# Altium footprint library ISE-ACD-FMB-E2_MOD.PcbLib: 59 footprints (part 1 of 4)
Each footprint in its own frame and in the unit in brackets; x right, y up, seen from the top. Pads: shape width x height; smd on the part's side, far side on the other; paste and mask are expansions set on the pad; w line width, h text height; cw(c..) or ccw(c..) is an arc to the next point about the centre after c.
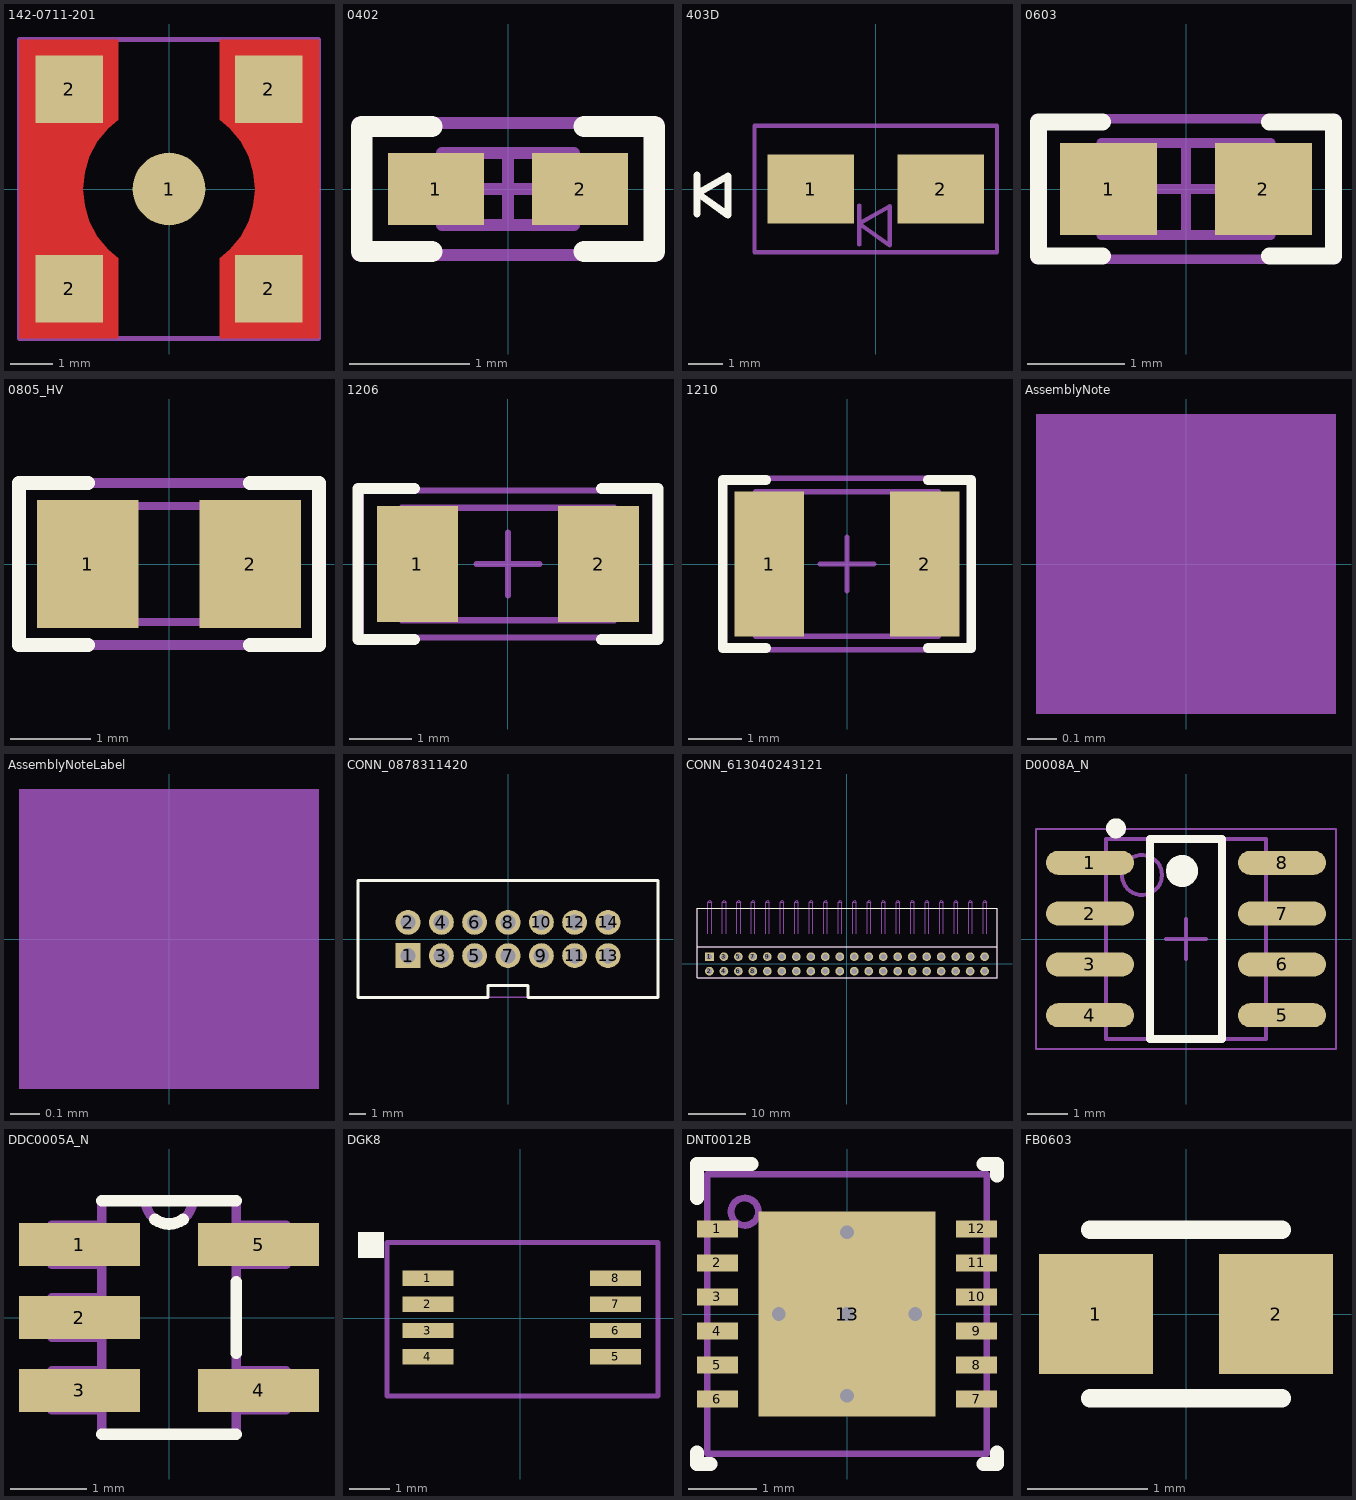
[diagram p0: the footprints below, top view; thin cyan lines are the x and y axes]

## 142-0711-201 [mil] "Emerson Connectivity recommended land pattern"
height 353
pads (5):
  round 68 smd: 1(0,0)
  rect 63x63 smd: 2(-93.5,-93.5) 2(-93.5,93.5) 2(93.5,-93.5) 2(93.5,93.5)
Top Layer:
  region: 140.5,-140 47.5,-140 47.5,-64.83 57.02,-57.02 67.05,-44.8 74.5,-30.86 79.09,-15.73 80.64,0 79.09,15.73 74.5,30.86 67.05,44.8 57.02,57.02 47.5,64.83 47.5,140 140.5,140
  region: -47.5,64.83 -57.02,57.02 -67.05,44.8 -74.5,30.86 -79.09,15.73 -80.64,0 -79.09,-15.73 -74.5,-30.86 -67.05,-44.8 -57.02,-57.02 -47.5,-64.83 -47.5,-140 -140.5,-140 -140.5,140 -47.5,140
Mechanical 5:
  lines w5: -140,-140 0,-140 140,-140 140,0 140,140 0,140 -140,140 -140,0 -140,-140
  text ".Designator" at 46,16 h36
3D body: height 338.6, standoff 0.6, extent -124.99,-124.99 125.1,125.1

## 0402 [mm] "0402 from SM-752 data"
height 0.6
pads (2):
  rect 0.8x0.6 smd: 1(-0.6,0) 2(0.6,0)
Top Overlay:
  lines w0.178: -0.635,-0.521 -1.219,-0.521 -1.219,0.521 -0.635,0.521 ; 0.635,-0.521 1.219,-0.521 1.219,0.521 0.635,0.521
Mechanical 5:
  lines w0.1: -1.25,-0.55 -1.25,0.55 1.25,0.55 1.25,-0.55 -1.25,-0.55
  text ".Designator" at -1.6,0.356 h0.91
Mechanical 13:
  lines w0.1: -0.35,-0.3 -0.35,0.3 ; 0.35,-0.3 0.35,0.3 ; -0.55,-0.3 0.55,-0.3 0.55,0.3 -0.55,0.3 -0.55,-0.3
Mechanical 15:
  lines w0.1: -0.3,0 0.3,0 ; 0,-0.3 0,0.3 ; -1.25,-0.55 1.25,-0.55 1.25,0.55 -1.25,0.55 -1.25,-0.55
3D body: height 0.6, standoff 0, extent 0.351,-0.299 0.549,0.299
3D body: height 0.6, standoff 0, extent -0.349,-0.299 0.349,0.299
3D body: height 0.6, standoff 0, extent -0.549,-0.299 -0.351,0.299

## 403D [mil]
pads (2):
  rect 100x80 smd: 1(-75,0) 2(75,0)
Top Overlay:
  lines w8: -206.35,-29 -206.35,16 ; -205.73,-5 -170.73,15 -170.73,-30 -205.73,-5
Mechanical 5:
  lines w5: -19,-64 -19,-19 ; -140,-73 140,-73 140,73 -140,73 -140,-73 ; -19,-40 16,-20 16,-65 -19,-40
  text ".Designator" at 29,27 h36

## 0603 [mm] "0603 from SM-752 data"
height 0.85
pads (2):
  rect 1x0.95 smd: 1(-0.8,0) 2(0.8,0)
Top Overlay:
  lines w0.178: -0.864,-0.691 -1.524,-0.691 -1.524,0.693 -0.864,0.693 ; 0.864,-0.691 1.524,-0.691 1.524,0.693 0.864,0.693
Mechanical 5:
  lines w0.1: -1.55,-0.725 -1.55,0.725 1.55,0.725 1.55,-0.725 -1.55,-0.725
  text ".Designator" at -1.448,0.965 h0.91
Mechanical 13:
  lines w0.1: -0.55,-0.475 -0.55,0.475 ; 0.55,-0.475 0.55,0.475 ; -0.875,-0.475 0.875,-0.475 0.875,0.475 -0.875,0.475 -0.875,-0.475
Mechanical 15:
  lines w0.1: -0.475,0 0.475,0 ; 0,-0.475 0,0.475 ; -1.55,-0.725 1.55,-0.725 1.55,0.725 -1.55,0.725 -1.55,-0.725
3D body: height 0.85, standoff 0, extent -0.874,-0.474 -0.551,0.474
3D body: height 0.85, standoff 0, extent -0.549,-0.474 0.549,0.474
3D body: height 0.85, standoff 0, extent 0.551,-0.474 0.874,0.474

## 0805_HV [mil] "0805 with 30mil clearance between pads"
height 43.31
pads (2):
  rect 50x63 smd: 1(-40,0) 2(40,0)
Top Overlay:
  lines w7: -40,-40 -74,-40 -74,0 -74,40 -40,40 ; 40,-40 74,-40 74,0 74,40 40,40
Mechanical 5:
  lines w5: -74,-40 -74,40 74,40 74,-40 -74,-40
  text ".Designator" at -38,-15 h36
Mechanical 13:
  lines w3.94: -25.59,-28.54 -25.59,28.54 ; 25.59,-28.54 25.59,28.54 ; -43.31,-28.54 43.31,-28.54 43.31,28.54 -43.31,28.54 -43.31,-28.54
3D body: height 43.31, standoff 0, extent -43.29,-28.52 -25.61,28.52
3D body: height 43.31, standoff 0, extent -25.57,-28.52 25.57,28.52
3D body: height 43.31, standoff 0, extent 25.61,-28.52 43.29,28.52

## 1206 [mm] "1206 from SM-752 data"
height 1.35
pads (2):
  rect 1.3x1.85 smd: 1(-1.45,0) 2(1.45,0)
Top Overlay:
  lines w0.178: -1.5,-1.21 -2.4,-1.21 -2.4,1.21 -1.5,1.21 ; 1.5,-1.21 2.4,-1.21 2.4,1.21 1.5,1.21
Mechanical 5:
  lines w0.1: -1.7,-0.9 1.7,-0.9 1.7,0.9 -1.7,0.9 -1.7,-0.9
  text ".Designator" at 1.092,0.483 h0.91
Mechanical 13:
  lines w0.1: -1.2,-0.9 -1.2,0.9 ; 1.2,-0.9 1.2,0.9 ; -1.7,-0.9 1.7,-0.9 1.7,0.9 -1.7,0.9 -1.7,-0.9
Mechanical 15:
  lines w0.1: -0.5,0 0.5,0 ; 0,-0.5 0,0.5 ; -2.35,-1.175 2.35,-1.175 2.35,1.175 -2.35,1.175 -2.35,-1.175
3D body: height 1.35, standoff 0, extent -1.699,-0.899 -1.201,0.899
3D body: height 1.35, standoff 0, extent -1.199,-0.899 1.199,0.899
3D body: height 1.35, standoff 0, extent 1.201,-0.899 1.699,0.899

## 1210 [mm] "1210 from SM-752 data"
height 1.35
pads (2):
  rect 1.3x2.7 smd: 1(-1.45,0) 2(1.45,0)
Top Overlay:
  lines w0.178: -1.511,-1.568 -2.316,-1.568 -2.316,1.568 -1.511,1.568 ; 1.511,-1.568 2.316,-1.568 2.316,1.568 1.511,1.568
Mechanical 5:
  lines w0.1: -1.7,-1.35 -1.7,1.35 1.7,1.35 1.7,-1.35 -1.7,-1.35
  text ".Designator" at 1.194,0.457 h0.91
Mechanical 13:
  lines w0.1: -1.2,-1.35 -1.2,1.35 ; 1.2,-1.35 1.2,1.35 ; -1.7,-1.35 1.7,-1.35 1.7,1.35 -1.7,1.35 -1.7,-1.35
Mechanical 15:
  lines w0.1: -0.5,0 0.5,0 ; 0,-0.5 0,0.5 ; -2.35,-1.6 2.35,-1.6 2.35,1.6 -2.35,1.6 -2.35,-1.6
3D body: height 1.35, standoff 0, extent 1.201,-1.349 1.699,1.349
3D body: height 1.35, standoff 0, extent -1.199,-1.349 1.199,1.349
3D body: height 1.35, standoff 0, extent -1.699,-1.349 -1.201,1.349

## AssemblyNote [mm] "Assembly Note"
Mechanical 5:
  rectangle: -0.508,-0.508 0.508,0.508
  text ".Comment" at 1.143,-0.508 h1.02
  text ".Designator" at -4.429,-0.604 h1.02

## AssemblyNoteLabel [mm] "Assembly Note for PCB Labels"
Mechanical 5:
  rectangle: -0.508,-0.508 0.508,0.508
  text "Install label in silkscreened box after final wash.  Text shall be 8 pt font.  Text shall be per the Label Table in the PDF schematic." at 1.143,-0.508 h1.02
  text ".Designator" at -4.81,-0.629 h1.02

## CONN_0878311420 [mm] "Molex Inc 14POS 2MM VERT"
height 6.35
pads (14):
  rect 1.5x1.5 hole 0.914: 1(-6,-1)
  round 1.5 hole 0.914: 2(-6,1) 3(-4,-1) 4(-4,1) 5(-2,-1) 6(-2,1) 7(0,-1) 8(0,1) 9(2,-1) 10(2,1) 11(4,-1) 12(4,1) 13(6,-1) 14(6,1)
Top Overlay:
  lines w0.178: -9,-3.5 -1.2,-3.5 -1.2,-2.8 1.2,-2.8 1.2,-3.5 4.5,-3.5 9,-3.5 9,3.5 -9,3.5 -9,-3.5
Mechanical 5:
  lines w0.1: -9,-3.5 9,-3.5 9,3.5 -9,3.5 -9,-3.5
  text ".Designator" at 1.372,-2.184 h0.91

## CONN_613040243121 [mil]
pads (40):
  rect 60x60 hole 38: 1(-950,50)
  round 60 hole 38: 2(-950,-50) 3(-850,50) 4(-850,-50) 5(-750,50) 6(-750,-50) 7(-650,50) 8(-650,-50) 9(-550,50) 10(-550,-50) 11(-450,50) 12(-450,-50) 13(-350,50) 14(-350,-50) 15(-250,50) 16(-250,-50) 17(-150,50) 18(-150,-50) 19(-50,50) 20(-50,-50) 21(50,50) 22(50,-50) 23(150,50) 24(150,-50) 25(250,50) 26(250,-50) 27(350,50) 28(350,-50) 29(450,50) 30(450,-50) 31(550,50) 32(550,-50) 33(650,50) 34(650,-50) 35(750,50) 36(750,-50) 37(850,50) 38(850,-50) 39(950,50) 40(950,-50)
Top Overlay:
  lines w6: -1036,120 1036,120 ; -1035,-95.5 -1035,385 1036,385 1036,-95.5 -1035,-95.5
Mechanical 5:
  lines w5: -1036,120 1036,120 ; -1035,-95.5 1036,-95.5 1036,385 -1035,385 -1035,-95.5
  text ".Designator" at -73,-20 h36
Mechanical 16:
  lines w1: -960.5,210 -960.5,427.5 ; -935.5,210 -935.5,427.5 ; -860.5,210 -860.5,427.5 ; -835.5,210 -835.5,427.5 ; -760.5,210 -760.5,427.5 ; -735.5,210 -735.5,427.5 ; -660.5,210 -660.5,427.5 ; -635.5,210 -635.5,427.5 ; -560.5,210 -560.5,427.5 ; -535.5,210 -535.5,427.5 ; -460.5,210 -460.5,427.5 ; -435.5,210 -435.5,427.5 ; -360.5,210 -360.5,427.5 ; -335.5,210 -335.5,427.5 ; -260.5,210 -260.5,427.5 ; -235.5,210 -235.5,427.5 ; -160.5,210 -160.5,427.5 ; -135.5,210 -135.5,427.5 ; -60.5,210 -60.5,427.5 ; -35.5,210 -35.5,427.5 ; 39.5,210 39.5,427.5 ; 64.5,210 64.5,427.5 ; 139.5,210 139.5,427.5 ; 164.5,210 164.5,427.5 ; 239.5,210 239.5,427.5 ; 264.5,210 264.5,427.5 ; 339.5,210 339.5,427.5 ; 364.5,210 364.5,427.5 ; 439.5,210 439.5,427.5 ; 464.5,210 464.5,427.5 ; 539.5,210 539.5,427.5 ; 564.5,210 564.5,427.5 ; 639.5,210 639.5,427.5 ; 664.5,210 664.5,427.5 ; 739.5,210 739.5,427.5 ; 764.5,210 764.5,427.5 ; 839.5,210 839.5,427.5 ; 864.5,210 864.5,427.5 ; 939.5,210 939.5,427.5 ; 964.5,210 964.5,427.5 ; -960.5,427.5 -948,440 -935.5,427.5 ; -960.5,427.5 -935.5,427.5 ; -860.5,427.5 -835.5,427.5 ; -860.5,427.5 -848,440 -835.5,427.5 ; -760.5,427.5 -748,440 -735.5,427.5 ; -760.5,427.5 -735.5,427.5 ; -660.5,427.5 -648,440 -635.5,427.5 ; -660.5,427.5 -635.5,427.5 ; -560.5,427.5 -548,440 -535.5,427.5 ; -560.5,427.5 -535.5,427.5 ; -460.5,427.5 -435.5,427.5 ; -460.5,427.5 -448,440 -435.5,427.5 ; -360.5,427.5 -348,440 -335.5,427.5 ; -360.5,427.5 -335.5,427.5 ; -260.5,427.5 -248,440 -235.5,427.5 ; -260.5,427.5 -235.5,427.5 ; -160.5,427.5 -148,440 -135.5,427.5 ; -160.5,427.5 -135.5,427.5 ; -60.5,427.5 -48,440 -35.5,427.5 ; -60.5,427.5 -35.5,427.5 ; 39.5,427.5 64.5,427.5 ; 39.5,427.5 52,440 64.5,427.5 ; 139.5,427.5 164.5,427.5 ; 139.5,427.5 152,440 164.5,427.5 ; 239.5,427.5 264.5,427.5 ; 239.5,427.5 252,440 264.5,427.5 ; 339.5,427.5 352,440 364.5,427.5 ; 339.5,427.5 364.5,427.5 ; 439.5,427.5 452,440 464.5,427.5 ; 439.5,427.5 464.5,427.5 ; 539.5,427.5 552,440 564.5,427.5 ; 539.5,427.5 564.5,427.5 ; 639.5,427.5 652,440 664.5,427.5 ; 639.5,427.5 664.5,427.5 ; 739.5,427.5 752,440 764.5,427.5 ; 739.5,427.5 764.5,427.5 ; 839.5,427.5 852,440 864.5,427.5 ; 839.5,427.5 864.5,427.5 ; 939.5,427.5 952,440 964.5,427.5 ; 939.5,427.5 964.5,427.5

## D0008A_N [mm] "SOIC, 8-Leads, Body 4.9x3.9mm, Pitch 1.27mm, IPC Medium Density"
height 1.75
pads (8):
  oval 2.2x0.6 smd: 1(-2.4,1.905) 2(-2.4,0.635) 3(-2.4,-0.635) 4(-2.4,-1.905) 5(2.4,-1.905) 6(2.4,-0.635) 7(2.4,0.635) 8(2.4,1.905)
Top Overlay:
  circle w0.4: c-0.1,1.7 r0.2
  circle w0.25: c-1.753,2.767 r0.125
  lines w0.2: -0.9,-2.5 0.9,-2.5 0.9,2.5 -0.9,2.5 -0.9,-2.5
Mechanical 5:
  circle w0.1: c-1.1,1.6 r0.5
  lines w0.1: -2,-2.5 2,-2.5 2,2.5 -2,2.5 -2,-2.5
  text ".Designator" at -0.279,0.914 h0.91
Mechanical 15:
  lines w0.05: -3.75,-2.75 3.75,-2.75 3.75,2.75 -3.75,2.75 -3.75,-2.75
  lines w0.1: -0.5,0 0.5,0 ; 0,-0.5 0,0.5
3D body: height 1.75, standoff 0.1, extent -2,-2.5 2,2.5

## DDC0005A_N [mil]
height 43.31
pads (5):
  rect 62x22 smd: 1(-46,37.4) 2(-46,0) 3(-46,-37.4) 4(46,-37.4) 5(46,37.4)
Top Overlay:
  lines w6: -34.5,-60 34.5,-60 ; -34.5,60 34.5,60 ; -7.14,50.35 ccw(c0,60) 7.14,50.35 ; 34.5,-18.3 34.5,18.3
Mechanical 5:
  lines w5: -12,60 ccw(c0,60) 12,60 ; -60,-47.4 -34.5,-47.4 -34.5,-27.4 -60,-27.4 -60,-47.4 ; -60,-10 -34.5,-10 -34.5,10 -60,10 -60,-10 ; -60,27.4 -34.5,27.4 -34.5,47.4 -60,47.4 -60,27.4 ; -34.5,-60 -34.5,60 34.5,60 34.5,-60 -34.5,-60 ; 34.5,-47.4 60,-47.4 60,-27.4 34.5,-27.4 34.5,-47.4 ; 34.5,27.4 60,27.4 60,47.4 34.5,47.4 34.5,27.4
  text ".Designator" at 16.18,-40.04 h30
3D body: height 23.62, standoff 0, extent -59.98,-9.98 -34.52,9.98
3D body: height 23.62, standoff 0, extent 34.52,27.42 59.98,47.38
3D body: height 23.62, standoff 0, extent 34.52,-47.38 59.98,-27.42
3D body: height 23.62, standoff 0, extent -59.98,27.42 -34.52,47.38
3D body: height 23.62, standoff 0, extent -59.98,-47.38 -34.52,-27.42
3D body: height 43.31, standoff 0, extent -34.5,47.74 34.52,60.02
3D body: height 43.31, standoff 0, extent -34.48,-59.98 34.48,59.98

## DGK8 [mil]
pads (8):
  rect 50x15 smd mask+2: 1(-90.2,39) 2(-90.2,13.4) 3(-90.2,-12.2) 4(-90.2,-37.8) 5(93.4,-37.8) 7(93.4,13.4) 8(93.4,39)
  rect 50x15 smd paste+0 mask+2: 6(93.4,-12.2)
Top Overlay:
  region: -158.5,84 -133.5,84 -133.5,59 -158.5,59
Mechanical 5:
  lines w5: -130.2,-76 134.8,-76 134.8,74 -130.2,74 -130.2,-76
  text "*" at -105,30 h40
  text ".Designator" at -43,-16 h36

## DNT0012B [mm] "SON, 12-Leads, Body 4x4mm, Pitch 0.5mm"
height 0.8
pads (13):
  rect 0.6x0.25 smd mask+0.051: 1(-1.9,1.25) 2(-1.9,0.75) 3(-1.9,0.25) 4(-1.9,-0.25) 5(-1.9,-0.75) 6(-1.9,-1.25) 7(1.9,-1.25) 8(1.9,-0.75) 9(1.9,-0.25) 10(1.9,0.25) 11(1.9,0.75) 12(1.9,1.25)
  rect 2.6x3 smd paste-1.3 mask+0.051: 13(0,0)
via 0,0 diameter 0.508 hole 0.203
via 1,0 diameter 0.508 hole 0.203
via -1,0 diameter 0.508 hole 0.203
via 0,-1.2 diameter 0.508 hole 0.203
via 0,1.2 diameter 0.508 hole 0.203
Top Overlay:
  lines w0.2: -2.2,-2.025 -2.2,-2.2 -2,-2.2 ; -2.2,1.7 -2.2,2.2 -1.4,2.2 ; 2,-2.2 2.2,-2.2 2.2,-2.025 ; 2,2.2 2.2,2.2 2.2,2.025
Top Paste:
  rectangle: 0.1,-1.41 1.248,-0.1
  region: -0.1,-0.1 -1.248,-0.1 -1.248,-1.41 -0.1,-1.41
  region: -0.1,1.41 -1.248,1.41 -1.248,0.1 -0.1,0.1
  rectangle: 0.1,0.1 1.248,1.41
Mechanical 5:
  circle w0.1: c-1.5,1.5 r0.2
  lines w0.1: -2.05,-2.05 -2.05,2.05 2.05,2.05 2.05,-2.05 -2.05,-2.05
  text ".Designator" at -0.406,1.143 h0.91
3D body: height 0.8, standoff 0, extent -2.049,-2.049 2.049,2.049
3D body: height 0.81, standoff 0.5, extent -1.703,1.297 -1.297,1.703

## FB0603 [mm]
height 0.95
pads (2):
  rect 0.95x1 smd: 1(-0.75,0) 2(0.75,0)
Top Overlay:
  lines w0.152: -0.8,-0.703 0.8,-0.703 ; -0.8,0.703 0.8,0.703
Mechanical 15:
  lines w0.025: -0.8,-0.4 -0.8,0.4 ; 0.8,-0.4 0.8,0.4
  lines w0.1: -0.8,-0.4 -0.8,0.4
